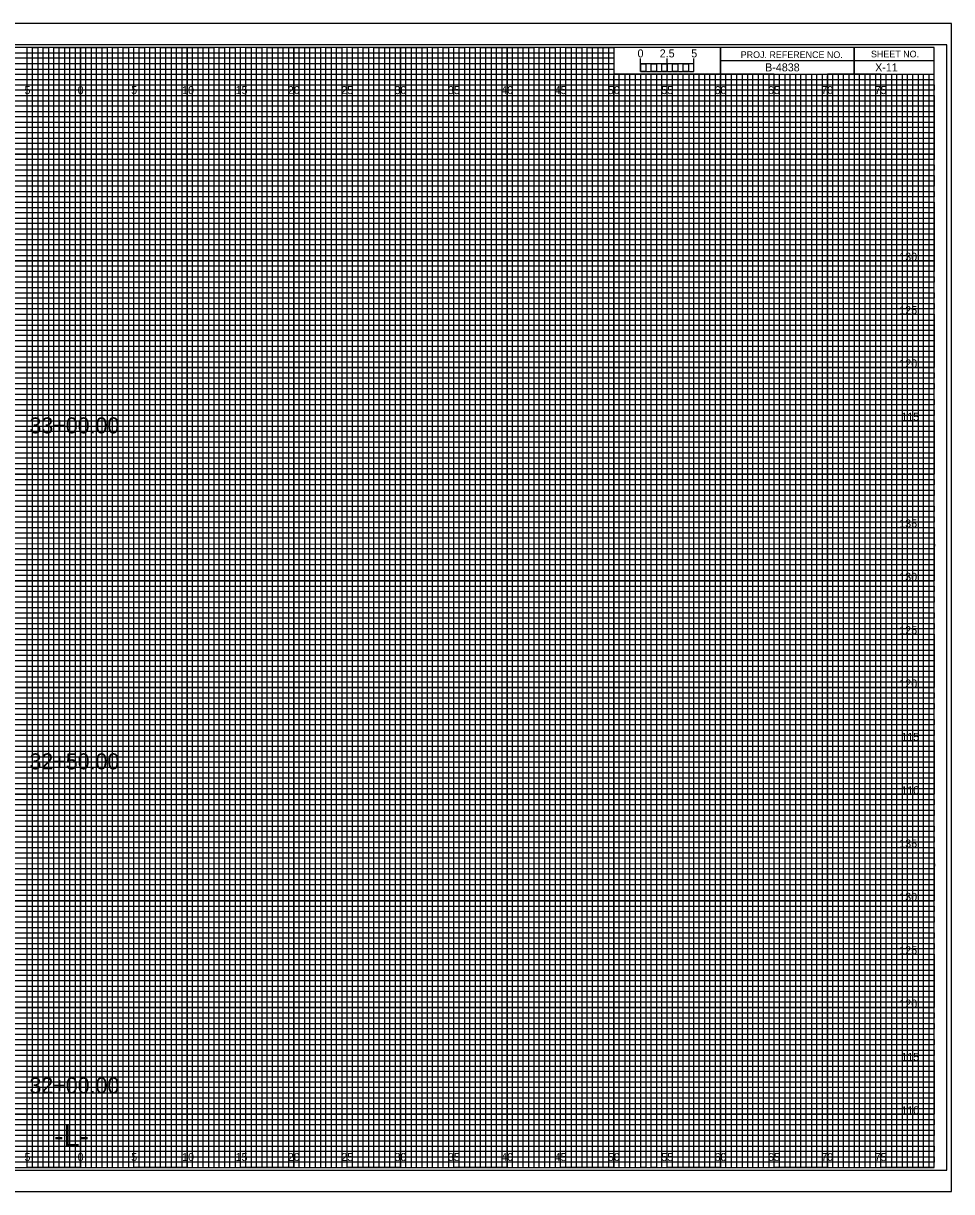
# Model space of a CAD drawing. Extents: x -7 to 182, y -2 to 1647.
# Drawn here: x 74.6 to 161.7, y 987.8 to 1097.2 of the extents above; entities that cross this region are included whole.
import ezdxf

# ---------------------------------------------------------------- set-up
doc = ezdxf.new("R2010")
doc.units = 0
for name, color, linetype in [('Exist CMT Pavement', 7, 'Continuous'), ('Exist Cross Section Cell', 7, 'Continuous'), ('Exist XS Ground Line', 7, 'Continuous'), ('Prop CMT Pvmt Course 1', 7, 'Continuous'), ('Prop CMT Pvmt Course 2', 7, 'Continuous'), ('Prop CMT Pvmt Course 2 Wedge', 7, 'Continuous'), ('Prop CMT Pvmt Course 3', 7, 'Continuous'), ('Prop CMT Pvmt Surface', 7, 'Continuous'), ('Prop CMT Pvmt Surface Shoulder', 7, 'Continuous'), ('Prop CMT Pvmt Wedge Surface 1', 7, 'Continuous'), ('Prop CMT Pvmt Wedge Surface 2', 7, 'Continuous'), ('Prop CMT Pvmt Wedge Surface 3', 7, 'Continuous'), ('Prop CMT Shld Paved Course 1', 7, 'Continuous'), ('Prop CMT Shld Paved Course 2', 7, 'Continuous'), ('Prop CMT Shld Paved Course 3', 7, 'Continuous'), ('Prop CMT Slope Grass', 7, 'Continuous'), ('Prop CMT Subgrade Earthwork', 7, 'Continuous')]:
    doc.layers.add(name, color=color, linetype=linetype)

msp = doc.modelspace()

# ---------------------------------------------------------------- linework, layer by layer
at = {"layer": 'Exist XS Ground Line'}
for p, q in [((75, 1095), (70, 1095)), ((75, 990), (75, 1095)), ((85, 1095), (80, 1095)), ((80, 1095), (80, 990)), ((85, 990), (85, 1095)), ((95, 1095), (90, 1095)), ((90, 1095), (90, 990)), ((95, 990), (95, 1095)), ((105, 1095), (100, 1095)), ((100, 1095), (100, 990)), ((105, 990), (105, 1095)), ((115, 1095), (110, 1095)), ((110, 1095), (110, 990)), ((115, 990), (115, 1095)), ((125, 1095), (120, 1095)), ((120, 1095), (120, 990)), ((125, 990), (125, 1095)), ((130, 1095), (130, 990)), ((135, 990), (135, 1092.5)), ((145, 1092.5), (140, 1092.5)), ((140, 1092.5), (140, 990)), ((145, 990), (145, 1092.5)), ((155, 1092.5), (150, 1092.5)), ((150, 1092.5), (150, 990)), ((155, 990), (155, 1092.5)), ((80, 990), (75, 990)), ((90, 990), (85, 990)), ((100, 990), (95, 990)), ((110, 990), (105, 990)), ((120, 990), (115, 990)), ((130, 990), (125, 990)), ((140, 990), (135, 990)), ((150, 990), (145, 990)), ((160, 990), (155, 990)), ((160, 990), (160, 990))]:
    msp.add_line(p, q, dxfattribs=at)
for points in [[(0, 1090), (160, 1090), (160, 1085), (0, 1085)], [(0, 1080), (160, 1080), (160, 1075), (0, 1075)], [(0, 1070), (160, 1070), (160, 1065), (0, 1065)], [(0, 1060), (160, 1060), (160, 1055), (0, 1055)], [(0, 1050), (160, 1050), (160, 1045), (0, 1045)], [(0, 1040), (160, 1040), (160, 1035), (0, 1035)], [(0, 1030), (160, 1030), (160, 1025), (0, 1025)], [(0, 1020), (160, 1020), (160, 1015), (0, 1015)], [(0, 1010), (160, 1010), (160, 1005), (0, 1005)], [(0, 1000), (160, 1000), (160, 995), (0, 995)]]:
    msp.add_lwpolyline(points, dxfattribs=at)
at = {"layer": 'Prop CMT Pvmt Course 2'}
for p, q in [((132.5, 1092.75), (132.5, 1093.95)), ((132.5, 1093.45), (132.5, 1093.95)), ((135, 1092.75), (135, 1093.95)), ((137.5, 1092.75), (137.5, 1093.95)), ((137.5, 1093.45), (137.5, 1093.95))]:
    msp.add_line(p, q, dxfattribs=at)
for points in [[(137.5, 1093.45), (132.5, 1093.45), (132.5, 1092.75), (137.5, 1092.75)], [(132.5, 1093.45), (133, 1093.45), (133, 1092.75), (132.5, 1092.75)], [(133.5, 1093.45), (134, 1093.45), (134, 1092.75), (133.5, 1092.75)], [(134.5, 1093.45), (135, 1093.45), (135, 1092.75), (134.5, 1092.75)], [(135.5, 1093.45), (136, 1093.45), (136, 1092.75), (135.5, 1092.75)], [(136.5, 1093.45), (137, 1093.45), (137, 1092.75), (136.5, 1092.75)]]:
    msp.add_lwpolyline(points, close=True, dxfattribs=at)
at = {"layer": 'Prop CMT Pvmt Course 3'}
msp.add_lwpolyline([(-6.7, 987.75), (161.65, 987.75), (161.65, 1097.25), (-6.7, 1097.25)], close=True, dxfattribs=at)
at = {"layer": 'Prop CMT Pvmt Wedge Surface 1'}
for p, q in [((0, 1094.5), (130, 1094.5)), ((130, 1093.99), (0, 1093.99)), ((130, 1094.5), (130, 1093.99)), ((0, 1093.5), (130, 1093.5)), ((130, 1092.94), (0, 1092.94)), ((130, 1093.5), (130, 1092.94)), ((0, 1092), (160, 1092))]:
    msp.add_line(p, q, dxfattribs=at)
for points in [[(0, 1091.5), (135, 1091.5), (160, 1091.5), (160, 1091), (0, 1091)], [(0, 1090.5), (160, 1090.5), (160, 1089.5), (0, 1089.5)], [(0, 1089), (160, 1089), (160, 1088.5), (0, 1088.49)], [(0, 1088), (160, 1088), (160, 1087), (0, 1087)], [(0, 1086.5), (160, 1086.5), (160, 1086), (0, 1086)], [(0, 1085.5), (160, 1085.5), (160, 1084.5), (0, 1084.5)], [(0, 1084), (160, 1084), (160, 1083.5), (0, 1083.5)], [(0, 1083), (160, 1083), (160, 1082), (0, 1082)], [(0, 1081.5), (160, 1081.5), (160, 1081), (0, 1081)], [(0, 1080.5), (160, 1080.5), (160, 1079.5), (0, 1079.5)], [(0, 1079), (160, 1079), (160, 1078.5), (0, 1078.5)], [(0, 1078), (160, 1078), (160, 1076.97), (160, 1076.5), (160, 1076), (0, 1076)], [(0, 1077), (160, 1077), (160, 1076.5), (0, 1076.5)], [(0, 1075.5), (160, 1075.5), (160, 1074.5), (0, 1074.52)], [(0, 1074.52), (160, 1074.5), (160, 1074), (0, 1074)], [(0, 1073.5), (160, 1073.5), (160, 1073), (0, 1073)], [(0, 1072), (160, 1072), (160, 1071.5), (0, 1071.5)], [(0, 1071), (160, 1071), (160, 1070.5), (0, 1070.5)], [(-0.04, 1069.44), (160, 1069.44), (160, 1068.94), (-0.04, 1068.94)], [(0, 1068.5), (160, 1068.5), (160, 1068), (0, 1068)], [(0, 1067), (160, 1067), (160, 1066.5), (0, 1066.5)], [(0, 1066), (160, 1066), (160, 1065.5), (0, 1065.5)], [(0, 1064.5), (160, 1064.5), (160, 1064), (0, 1064)], [(0, 1063.5), (160, 1063.5), (160, 1063), (0, 1063)], [(0, 1062), (160, 1062), (160, 1061.5), (0, 1061.5)], [(0, 1061), (160, 1061), (160, 1060.5), (0, 1060.5)], [(0, 1059.5), (160, 1059.5), (160, 1058.99), (0, 1059)], [(0, 1058.5), (160, 1058.5), (160, 1058), (0, 1058)], [(0, 1057), (160, 1057), (160, 1056.5), (0, 1056.5)], [(0, 1056), (160, 1056), (160, 1055.5), (0, 1055.5)], [(0, 1054.5), (160, 1054.5), (160, 1054), (0, 1054)], [(0, 1053.5), (160, 1053.5), (160, 1053), (0, 1053)], [(0, 1052), (160, 1052), (160, 1051.5), (0, 1051.5)], [(0, 1051), (160, 1051), (160, 1050.5), (0, 1050.5)], [(0, 1049.5), (160, 1049.5), (160, 1049), (0, 1049)], [(0, 1048.5), (160.03, 1048.45), (160, 1048), (0, 1048)], [(0, 1047), (160, 1047), (160, 1046.5), (0, 1046.5)], [(0, 1046), (160, 1046), (160, 1045.5), (0, 1045.5)], [(0, 1044.5), (160, 1044.5), (160, 1044), (0, 1044)], [(0, 1043.5), (160, 1043.5), (160, 1043), (0, 1043)], [(0, 1042), (160, 1042), (160, 1041.5), (0, 1041.5)], [(0, 1041), (160, 1041), (160, 1040.5), (0, 1040.5)], [(0, 1039.5), (160, 1039.5), (160, 1039), (0, 1039)], [(0, 1038.5), (160, 1038.5), (160, 1038), (0, 1038)], [(0, 1037), (160, 1037), (160, 1036.5), (0, 1036.5)], [(0, 1036), (160, 1036), (160, 1035.5), (0, 1035.5)], [(0, 1034.5), (160, 1034.5), (160, 1034), (0, 1034)], [(0, 1033.5), (160, 1033.5), (160, 1033), (0, 1033)], [(0, 1032), (160, 1032), (160, 1031.5), (0, 1031.5)], [(0, 1031), (160, 1031), (160, 1030.5), (0, 1030.5)], [(0, 1029.5), (160, 1029.5), (160, 1028.99), (0, 1029)], [(0, 1028.5), (160, 1028.5), (160, 1028), (0, 1028)], [(0, 1027), (160, 1027), (160, 1026.5), (0, 1026.5)], [(0, 1026), (160, 1026), (160, 1025.5), (0, 1025.5)], [(0, 1024.5), (160, 1024.5), (160, 1024), (0, 1024)], [(0, 1023.5), (160, 1023.5), (160, 1023), (0, 1023)], [(0, 1022), (160, 1022), (160, 1021.5), (0, 1021.5)], [(0, 1021), (160, 1021), (160, 1020.5), (0, 1020.5)], [(0, 1019.5), (160, 1019.5), (160, 1019), (0, 1019)], [(0, 1018.5), (160.03, 1018.46), (160, 1018), (0, 1018)], [(0, 1017), (160, 1017), (160, 1016.5), (0, 1016.5)], [(0, 1016), (160, 1016), (160, 1015.5), (0, 1015.5)], [(0, 1014.5), (160, 1014.5), (160, 1014), (0, 1014)], [(0, 1013.5), (160, 1013.5), (160, 1013), (0, 1013)], [(0, 1012), (160, 1012), (160, 1011.5), (0, 1011.5)], [(0, 1011), (160, 1011), (160, 1010.5), (0, 1010.5)], [(0, 1009.5), (160, 1009.5), (160, 1009), (0, 1009)], [(0, 1008.5), (160, 1008.5), (160, 1008), (0, 1008)], [(0, 1007), (160, 1007), (160, 1006.5), (0, 1006.5)], [(0, 1006), (160, 1006), (160, 1005.5), (0, 1005.5)], [(0, 1004.5), (160, 1004.5), (160, 1004), (0, 1004)], [(0, 1003.5), (160, 1003.5), (160, 1003), (0, 1003)], [(0, 1002), (160, 1002), (160, 1001.5), (0, 1001.5)], [(0, 1001), (160, 1001), (160, 1000.5), (0, 1000.5)], [(0, 999.5), (160, 999.5), (160, 999), (0, 999)], [(0, 998.5), (160, 998.5), (160, 998), (0, 998)], [(0, 997), (160, 997), (160, 996.5), (0, 996.5)], [(0, 996), (160, 996), (160, 995.5), (0, 995.5)], [(0, 994.5), (160, 994.5), (160, 994), (0, 994)], [(0, 993.5), (160, 993.5), (160, 993), (0, 993)], [(0, 992), (160, 992), (160, 991.5), (0, 991.5)], [(0, 991), (160, 991), (160, 990.5), (0, 990.5)]]:
    msp.add_lwpolyline(points, dxfattribs=at)
at = {"layer": 'Prop CMT Pvmt Wedge Surface 2'}
for p, q in [((152.5, 1095), (152.5, 1092.5)), ((152.5, 1092.5), (152.5, 1095)), ((160, 1093.75), (140, 1093.75)), ((140, 1093.75), (140, 1092.5)), ((140, 1092.5), (160, 1092.5))]:
    msp.add_line(p, q, dxfattribs=at)
for points in [[(160, 1095), (0, 1095), (0, 990), (160, 990)], [(140, 1095), (130, 1095), (130, 1092.52), (140, 1092.52)], [(160, 1095), (140, 1095), (140, 1092.5), (160, 1092.5)]]:
    msp.add_lwpolyline(points, close=True, dxfattribs=at)
at = {"layer": 'Prop CMT Pvmt Wedge Surface 3'}
for p, q in [((133.5, 1092.5), (133, 1092.5)), ((133, 1092.5), (133, 990)), ((133.5, 990), (133.5, 1092.5)), ((134.5, 1092.5), (134, 1092.5)), ((134, 1092.5), (134, 990)), ((134.5, 990), (134.5, 1092.5)), ((133, 990), (132.5, 990)), ((134, 990), (133.5, 990))]:
    msp.add_line(p, q, dxfattribs=at)
for points in [[(75, 990), (75.5, 990), (75.5, 1095), (76, 1095), (76, 990)], [(76, 990), (76.5, 990), (76.5, 1095), (77, 1095), (77, 990)], [(77.5, 990), (78, 990), (78, 1095), (78.5, 1095), (78.5, 990)], [(78.5, 990), (79, 990), (79, 1095), (79.5, 1095), (79.5, 990)], [(80, 990), (80.5, 990), (80.5, 1095), (81, 1095), (81, 990)], [(81, 990), (81.5, 990), (81.5, 1095), (82, 1095), (82, 990)], [(82.5, 990), (83, 990), (83, 1095), (83.5, 1095), (83.5, 990)], [(83.5, 990), (84, 990), (84, 1095), (84.5, 1095), (84.5, 990)], [(85, 990), (85.5, 990), (85.5, 1095), (86, 1095), (86, 990)], [(86, 990), (86.5, 990), (86.5, 1095), (87, 1095), (87, 990)], [(87.5, 990), (88, 990), (88, 1095), (88.5, 1095), (88.5, 990)], [(88.5, 990), (89, 990), (89, 1095), (89.5, 1095), (89.5, 990)], [(90, 990), (90.5, 990), (90.5, 1095), (91, 1095), (91, 990)], [(91, 990), (91.5, 990), (91.5, 1095), (92, 1095), (92, 990)], [(92.5, 990), (93, 990), (93, 1095), (93.5, 1095), (93.5, 990)], [(93.5, 990), (94, 990), (94, 1095), (94.5, 1095), (94.5, 990)], [(95, 990), (95.5, 990), (95.5, 1095), (96, 1095), (96, 990)], [(96, 990), (96.5, 990), (96.5, 1095), (97, 1095), (97, 990)], [(97.5, 990), (98, 990), (98, 1095), (98.5, 1095), (98.5, 990)], [(98.5, 990), (99, 990), (99, 1095), (99.5, 1095), (99.5, 990)], [(100, 990), (100.5, 990), (100.5, 1095), (101, 1095), (101, 990)], [(101, 990), (101.5, 990), (101.5, 1095), (102, 1095), (102, 990)], [(102.5, 990), (103, 990), (103, 1095), (103.5, 1095), (103.5, 990)], [(103.5, 990), (104, 990), (104, 1095), (104.5, 1095), (104.5, 990)], [(105, 990), (105.5, 990), (105.5, 1095), (106, 1095), (106, 990)], [(106, 990), (106.5, 990), (106.5, 1095), (107, 1095), (107, 990)], [(107.5, 990), (108, 990), (108, 1095), (108.5, 1095), (108.5, 990)], [(108.5, 990), (109, 990), (109, 1095), (109.5, 1095), (109.5, 990)], [(110, 990), (110.5, 990), (110.5, 1095), (111, 1095), (111, 990)], [(111, 990), (111.5, 990), (111.5, 1095), (112, 1095), (112, 990)], [(112.5, 990), (113, 990), (113, 1095), (113.5, 1095), (113.5, 990)], [(113.5, 990), (114, 990), (114, 1095), (114.5, 1095), (114.5, 990)], [(115, 990), (115.5, 990), (115.5, 1095), (116, 1095), (116, 990)], [(116, 990), (116.5, 990), (116.5, 1095), (117, 1095), (117, 990)], [(117.5, 990), (118, 990), (118, 1095), (118.5, 1095), (118.5, 990)], [(118.5, 990), (119, 990), (119, 1095), (119.5, 1095), (119.5, 990)], [(120, 990), (120.5, 990), (120.5, 1095), (121, 1095), (121, 990)], [(121, 990), (121.5, 990), (121.5, 1095), (122, 1095), (122, 990)], [(122.5, 990), (123, 990), (123, 1095), (123.5, 1095), (123.5, 990)], [(123.5, 990), (124, 990), (124, 1095), (124.5, 1095), (124.5, 990)], [(125, 990), (125.5, 990), (125.5, 1095), (126, 1095), (126, 990)], [(126, 990), (126.5, 990), (126.5, 1095), (127, 1095), (127, 990)], [(127.5, 990), (128, 990), (128, 1095), (128.5, 1095), (128.5, 990)], [(128.5, 990), (129, 990), (129, 1095), (129.5, 1095), (129.5, 990)], [(130, 990), (130.5, 990), (130.5, 1092.5), (131.01, 1092.5), (131.01, 990)], [(131, 990), (131.5, 990), (131.5, 1092.5), (132, 1092.5), (132, 990)], [(135, 990), (135.49, 990), (135.49, 1092.5), (136, 1092.5), (136, 990)], [(136, 990), (136.5, 990), (136.5, 1092.5), (137.03, 1092.5), (137.03, 990)], [(137.5, 990), (138, 990), (138, 1092.5), (138.5, 1092.5), (138.5, 990)], [(138.5, 990), (139, 990), (139, 1092.5), (139.5, 1092.5), (139.5, 990)], [(140, 990), (140.5, 990), (140.5, 1092.5), (141, 1092.5), (141, 990)], [(141, 990), (141.5, 990), (141.5, 1092.5), (142, 1092.5), (142, 990)], [(142.5, 990), (143, 990), (143, 1092.5), (143.5, 1092.5), (143.5, 990)], [(143.5, 990), (144, 990), (144, 1092.5), (144.5, 1092.5), (144.5, 990)], [(145, 990), (145.5, 990), (145.5, 1092.5), (146, 1092.5), (146, 990)], [(146, 990), (146.5, 990), (146.5, 1092.5), (147, 1092.5), (147, 990)], [(147.5, 990), (148, 990), (148, 1092.5), (148.5, 1092.5), (148.5, 990)], [(148.5, 990), (149, 990), (149, 1092.5), (149.5, 1092.5), (149.5, 990)], [(150, 990), (150.5, 990), (150.5, 1092.5), (151, 1092.5), (151, 990)], [(151, 990), (151.5, 990), (151.5, 1092.5), (152, 1092.5), (152, 990)], [(152.5, 990), (153, 990), (153, 1092.5), (153.5, 1092.5), (153.5, 990)], [(153.5, 990), (154, 990), (154, 1092.5), (154.5, 1092.5), (154.5, 990)], [(155, 990), (155.5, 990), (155.5, 1092.5), (156, 1092.5), (156, 990)], [(156, 990), (156.5, 990), (156.5, 1092.5), (157, 1092.5), (157, 990)], [(157.5, 990), (158, 990), (158, 1092.5), (158.5, 1092.5), (158.5, 990)], [(158.5, 990), (159, 990), (159, 1092.5), (159.5, 1092.5), (159.5, 990)]]:
    msp.add_lwpolyline(points, dxfattribs=at)
at = {"layer": 'Prop CMT Shld Paved Course 1'}
for p, q in [((75, 990), (75, 1095)), ((80, 990), (80, 1095)), ((85, 990), (85, 1095)), ((90, 990), (90, 1095)), ((95, 990), (95, 1095)), ((100, 990), (100, 1095)), ((105, 990), (105, 1095)), ((110, 990), (110, 1095)), ((115, 990), (115, 1095)), ((120, 990), (120, 1095)), ((125, 990), (125, 1095)), ((130, 990), (130, 1092.34)), ((135, 990), (135, 1092.34)), ((140, 990), (140, 1092.34)), ((145, 990), (145, 1092.34)), ((150, 990), (150, 1092.34)), ((155, 990), (155, 1092.34)), ((0, 1090), (160, 1090)), ((0, 1085), (160, 1085)), ((0, 1080), (160, 1080)), ((0, 1075), (160, 1075)), ((0, 1070), (160, 1070)), ((0, 1065), (160, 1065)), ((0, 1060), (160, 1060)), ((0, 1055), (160, 1055)), ((0, 1050), (160, 1050)), ((0, 1045), (160, 1045)), ((0, 1040), (160, 1040)), ((0, 1035), (160, 1035)), ((0, 1030), (160, 1030)), ((0, 1025), (160, 1025)), ((0, 1020), (160, 1020)), ((0, 1015), (160, 1015)), ((0, 1010), (160, 1010)), ((0, 1005), (160, 1005)), ((0, 1000), (160, 1000)), ((0, 995), (160, 995))]:
    msp.add_line(p, q, dxfattribs=at)
at = {"layer": 'Prop CMT Shld Paved Course 2'}
for p, q in [((161.65, 1097.25), (-6.7, 1097.25)), ((-6.7, 987.75), (161.65, 987.75))]:
    msp.add_line(p, q, dxfattribs=at)
at = {"layer": 'Prop CMT Slope Grass'}
msp.add_lwpolyline([(-5.4, 989.75), (161.2, 989.75), (161.2, 1095.25), (-5.4, 1095.25)], close=True, dxfattribs=at)
at = {"layer": 'Prop CMT Subgrade Earthwork'}
for points in [[(72.5, 990), (77.5, 990), (77.5, 1095), (82.5, 1095), (82.5, 990), (87.5, 990), (87.5, 1095), (92.5, 1095), (92.5, 990), (97.5, 990), (97.5, 1095), (102.5, 1095), (102.5, 990), (107.5, 990), (107.5, 1095), (112.5, 1095), (112.5, 990), (117.5, 990), (117.5, 1095), (122.5, 1095), (122.5, 990), (127.5, 990), (127.5, 1095), (129.97, 1095), (130, 1095), (130, 1092.5), (132.5, 1092.5), (132.5, 990), (137.5, 990), (137.5, 1092.5), (142.5, 1092.5), (142.5, 990), (147.5, 990), (147.5, 1092.5), (152.5, 1092.5), (152.5, 990), (157.5, 990), (157.5, 1092.5)], [(0, 1092.5), (137.5, 1092.5)], [(0, 1082.5), (160, 1082.5), (160, 1087.5), (0, 1087.5)], [(0, 1072.5), (160, 1072.5), (160, 1077.5), (0, 1077.5)], [(0, 1062.5), (160, 1062.5), (160, 1067.5), (0, 1067.5)], [(0, 1052.5), (160, 1052.5), (160, 1057.5), (0, 1057.5)], [(0, 1042.5), (160, 1042.5), (160, 1047.5), (0, 1047.5)], [(0, 1032.5), (160, 1032.5), (160, 1037.5), (0, 1037.5)], [(0, 1022.5), (160, 1022.5), (160, 1027.5), (0, 1027.5)], [(0, 1012.5), (160, 1012.5), (160, 1017.5), (0, 1017.5)], [(0, 1002.5), (160, 1002.5), (160, 1007.5), (0, 1007.5)], [(0, 992.5), (160, 992.5), (160, 997.5), (0, 997.5)]]:
    msp.add_lwpolyline(points, dxfattribs=at)

# ---------------------------------------------------------------- texts
at = {"layer": 'Exist CMT Pavement'}
for s, p in [('33+00.00', (75.21, 1058.82)), ('32+50.00', (75.21, 1027.33)), ('32+00.00', (75.21, 996.96))]:
    msp.add_text(s, height=1.5, dxfattribs=at).set_placement(p)
at = {"layer": 'Exist Cross Section Cell'}
for s, p in [('5', (74.74, 1090.62)), ('0', (79.73, 1090.62)), ('0', (79.73, 1090.62)), ('5', (84.74, 1090.62)), ('10', (89.52, 1090.62)), ('15', (94.53, 1090.62)), ('20', (99.43, 1090.62)), ('25', (104.44, 1090.62)), ('30', (109.43, 1090.62)), ('35', (114.44, 1090.62)), ('40', (119.43, 1090.62)), ('45', (124.44, 1090.62)), ('50', (129.43, 1090.62)), ('55', (134.44, 1090.62)), ('60', (139.43, 1090.62)), ('65', (144.44, 1090.62)), ('70', (149.43, 1090.62)), ('75', (154.44, 1090.62)), ('5', (74.74, 990.62)), ('0', (79.73, 990.62)), ('0', (79.73, 990.62)), ('5', (84.74, 990.62)), ('10', (89.52, 990.62)), ('15', (94.53, 990.62)), ('20', (99.43, 990.62)), ('25', (104.44, 990.62)), ('30', (109.43, 990.62)), ('35', (114.44, 990.62)), ('40', (119.43, 990.62)), ('45', (124.44, 990.62)), ('50', (129.43, 990.62)), ('55', (134.44, 990.62)), ('60', (139.43, 990.62)), ('65', (144.44, 990.62)), ('70', (149.43, 990.62)), ('75', (154.44, 990.62))]:
    msp.add_text(s, height=0.75, dxfattribs=at).set_placement(p)
at = {"layer": 'Prop CMT Pvmt Course 1'}
msp.add_text('-L-', height=2, dxfattribs=at).set_placement((77.53, 992))
at = {"layer": 'Prop CMT Pvmt Course 2'}
msp.add_text('0', height=0.75, dxfattribs=at).set_placement((132.21, 1094.06))
at = {"layer": 'Prop CMT Pvmt Course 2 Wedge'}
for s, p in [('2.5', (134.29, 1094.06)), ('5', (137.24, 1094.06))]:
    msp.add_text(s, height=0.75, dxfattribs=at).set_placement(p)
at = {"layer": 'Prop CMT Pvmt Surface'}
msp.add_text('X-11', height=0.75, dxfattribs=at).set_placement((154.48, 1092.75))
at = {"layer": 'Prop CMT Pvmt Surface Shoulder'}
msp.add_text('B-4838', height=0.75, dxfattribs=at).set_placement((144.17, 1092.75))
at = {"layer": 'Prop CMT Pvmt Wedge Surface 2'}
for s, p in [('PROJ. REFERENCE NO.', (141.88, 1094)), ('SHEET NO.', (154.09, 1094.06))]:
    msp.add_text(s, height=0.625, dxfattribs=at).set_placement(p)
at = {"layer": 'Prop CMT Shld Paved Course 3'}
for s, p in [('130', (156.74, 1075)), ('125', (156.74, 1070)), ('120', (156.75, 1065)), ('115', (156.93, 1060)), ('135', (156.74, 1050)), ('130', (156.74, 1045)), ('125', (156.74, 1040)), ('120', (156.75, 1035)), ('115', (156.93, 1030)), ('110', (156.94, 1025)), ('135', (156.74, 1020)), ('130', (156.74, 1015)), ('125', (156.74, 1010)), ('120', (156.75, 1005)), ('115', (156.93, 1000)), ('110', (156.94, 995))]:
    msp.add_text(s, height=0.75, dxfattribs=at).set_placement(p)

doc.saveas('drawing.dxf')
